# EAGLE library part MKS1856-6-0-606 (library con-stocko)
Serie MKS 1850 Lötstifte In-line, Raster 2.5 mm, Stiftwannen, stehend, mit Rastlasche Source: http://www.stocko.de/de/index.php?seite=ka_rfk2_mks1850.html&rubrik=Katalog+-+RFK+2 rfk_1850.pdf
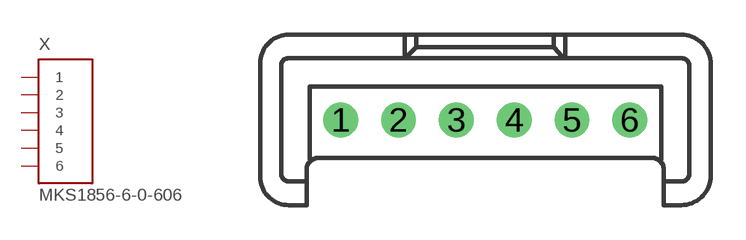
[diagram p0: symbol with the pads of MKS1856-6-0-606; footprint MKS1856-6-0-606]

Designator prefix X

## MKS1856-6-0-606 (OC_FARNELL: 1174959; OC_NEWARK: unknown)  [MKS1856-6-0-606]
1  1  in
2  2  in
3  3  in
4  4  in
5  5  in
6  6  in

## Footprint MKS1856-6-0-606 (pad centres in mm)
Serie MKS 1850 Lötstifte In-line, Raster 2.5 mm, Stiftwannen, stehend, mit Rastlasche Source: http://www.stocko.de/de/index.php?seite=ka_rfk2_mks1850.html&rubrik=Katalog+-+RFK+2 rfk_1850.pdf
drill 1 pad 1.422 round: 1 -6.25,0; 2 -3.75,0; 3 -1.25,0; 4 1.25,0; 5 3.75,0; 6 6.25,0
